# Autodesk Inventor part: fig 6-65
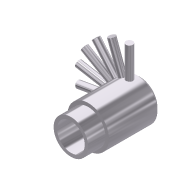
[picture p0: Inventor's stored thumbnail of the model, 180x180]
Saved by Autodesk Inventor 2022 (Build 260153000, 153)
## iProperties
Created: 2001-12
Part Number: fig 6-65
Document SubType Name: Modeling
Designer: Renu Muthoo
Density: 1 g/cm^3
Material: Generic
Appearance: Metal-AL-6061 (Polished)
Control State: 0
Master: False
Checked Out: False
Shininess: 77.0
Angle Display Precision: 2
Document Length Units: 11269
Document Angle Units: 11279
Document Time Units: 11290
Document Mass Units: 11283
Document Length Units Precision: 3
Document Angle Units Precision: 2
Compacted: True
Density: 0.0
Volumn: 0.0
Area: 0.0
PropertySet Name: Model Information
Author: Renu Muthoo
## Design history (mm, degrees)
sketch "Sketch2"
  geometry: L1 (-9.573, -4.327)-(-9.573, -5.327); L2 (-9.573, -5.327)-(-4.573, -5.327); L3 (-4.573, -5.327)-(-4.573, -6.327); L4 (-4.573, -6.327)-(9.427, -6.327); L5 (9.427, -6.327)-(10.427, -5.327); L6 (10.427, -5.327)-(10.427, -4.327); L7 (10.427, -4.327)-(-9.573, -4.327); L8 (-13.687, -0.327)-(14, -0.327)
  constraints: 16 end point, 5 parallel, 1 perpendicular, 1 vertical
  dimensions: "d9" = 20 distance of L6.end L1.start; "d10" = 5 distance of L1.end L2.end; "d11" = 12 diameter of L4 L8; "d12" = 10 diameter of L2 L8; "d13" = 8 diameter of L7 L8; "d14" = 45 deg angle of L5 L4; "d15" = 1 horizontal distance of L5.end L4.end
revolve "Revolution2" sketch "Sketch2" stored, may be unused: angle "d16" = 90 deg
workplane "Work Plane1"
workplane "Work Plane2"
sketch "Sketch3"
  geometry: L1 (-4, 8)-(4, 8) reference; C1 r 1 at (-0.098, 5)
  constraints: 1 centre point
  dimensions: "d18" = 3 distance from line of L1 C1.centre; "d19" = 2 diameter of C1
extrude "Extrusion1" join sketch "Sketch3" distance "d20" = 10; taper "d21" = 0 deg
pattern_circular "Circular Pattern3" dims angle "d29" = 20 deg
body "Solid1"
other parameters: "d17" = -1
